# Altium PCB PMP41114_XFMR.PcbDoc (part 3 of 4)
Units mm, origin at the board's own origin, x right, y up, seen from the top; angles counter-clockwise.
Board outline 70 x 173.04 mm, 10 copper layers (Top Layer, Layer 2, Layer 3, Layer 4, Layer 5, Layer 6, Layer 7, Layer 8, Layer 9, Bottom Layer 1), stack 2.98 mm thick; 147 components, 149 nets, 547 pads, 972 vias.
Unrouted connection lines stored in the file: 2.
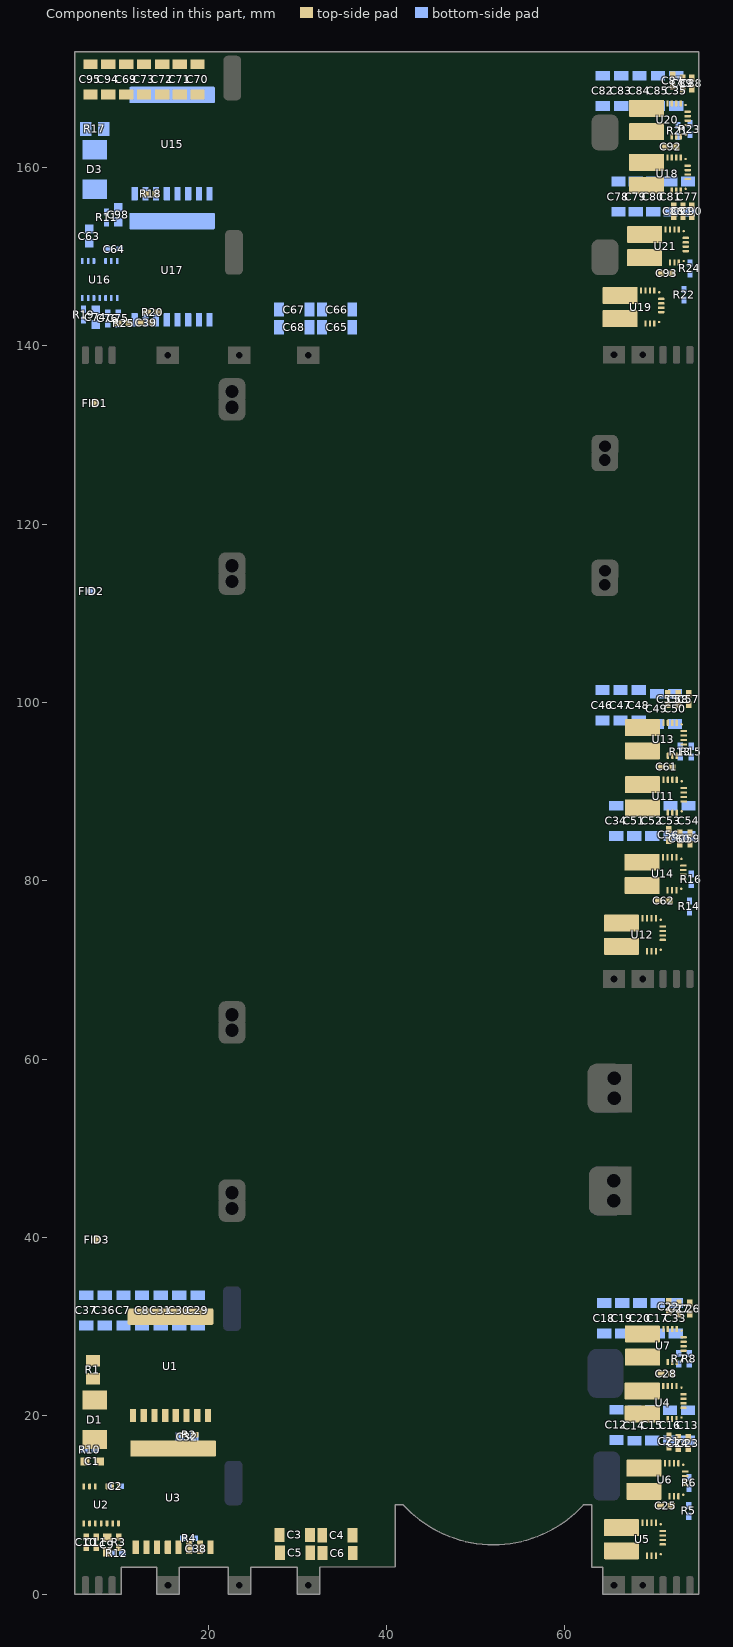
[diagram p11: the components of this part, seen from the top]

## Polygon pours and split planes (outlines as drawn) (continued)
Pri-Middle_2 on Layer 3 "LAYER_3_PRI-MIDDLE_2_P393" (solid, remove dead copper, pour order 393): 33.543,7.627 33.956,7.214 33.956,3.473 31.984,1.5 29.993,1.5 29.993,7.094 30.526,7.627
no net on Layer 5 "LAYER_5_NONET_P415" (solid, remove dead copper, pour order 415): 5.5,9.945 8.693,13.138 10.372,13.138 10.473,13.037 10.473,3.377 9.839,2.743 9.839,0.768 5.532,0.768 5.5,0.8
Pri-Mid1_2 on Layer 5 "LAYER_5_PRI-MID1_2_P625" (solid, remove dead copper, pour order 625): 18 vertices, not listed, extent 22.496,3.231 37.639,14.568
Pri-Mid1_5 on Layer 5 "LAYER_5_PRI-MID1_5_P622" (solid, remove dead copper, pour order 622): 28.819,141.744 26.926,141.744 26.926,147.57 37.473,147.57 37.473,146.475 37.473,141.522 34.617,141.522 34.617,145.888 34.12,146.385 29.713,146.385 29.107,145.78 29.107,142.032
Pri-SW_5 on Layer 5 "LAYER_5_PRI-SW_5_P468" (solid, remove dead copper, pour order 468): 49 vertices, not listed, extent 21.519,143.513 62.713,170.403
54Vout_5 on Layer 5 "LAYER_5_54VOUT_5_P589" (solid, remove dead copper, pour order 589): 63.146,172.5 63.146,157.183 64.767,157.183 64.767,154.137 63.146,154.137 63.146,141.018 64.25,141.018 64.25,138 75,138 75,172.5
54Vout_2 on Layer 5 "LAYER_5_54VOUT_2_P435" (solid, remove dead copper, pour order 435): 63.394,34.5 63.394,19.183 64.767,19.183 64.767,16.137 63.394,16.137 63.394,3.018 64.25,3.018 64.25,0 75,0 75,34.5
54Vout_4 on Layer 5 "LAYER_5_54VOUT_4_P568" (solid, remove dead copper, pour order 568): 63,103 63,89.592 65.232,89.592 65.232,80.979 63,78.747 63,71.018 64.25,71.018 64.25,68 75,68 75,103
Pri-Middle_5 on Layer 5 "LAYER_5_PRI-MIDDLE_5_P559" (solid, remove dead copper, pour order 559): 33.543,145.589 33.956,145.175 33.956,141.04 32.563,141.04 32.5,140.962 32.5,139.462 29.993,139.462 29.993,145.055 30.526,145.589
Pri-SW_2 on Layer 5 "LAYER_5_PRI-SW_2_P454" (solid, remove dead copper, pour order 454): 40 vertices, not listed, extent 36.298,37.799 64.006,64.687
B-_5 on Layer 5 "LAYER_5_B-_5_P534" (solid, remove dead copper, pour order 534): 4.985,141.046 5.001,147.544 5.437,147.544 8.397,150.504 20.543,150.504 20.543,141.742 19.807,141.006 16.771,141.006 16.771,138.962 14.155,138.962 14.155,141.046
B-_5 on Layer 5 "LAYER_5_B-_5_P519" (solid, remove dead copper, pour order 519): 5.498,172.468 21.325,172.468 21.325,170.307 5.498,170.307
B+_5 on Layer 5 "Layer 5-B+_5" (solid, remove dead copper, pour order 513): 5.5,151.038 21.238,151.038 21.238,140.962 22.243,140.962 22.243,139.303 24.784,139.303 24.784,140.962 26.28,140.962 26.28,151.862 20.899,155.75 20.899,169.482 5.5,169.482
Sec-SWB_4 on Layer 5 "LAYER_5_SEC-SWB_4_P497" (solid, remove dead copper, pour order 497): 34 vertices, not listed, extent 38.632,73.616 70.621,100.504
Pri-SW_5 on Layer 5 "LAYER_5_PRI-SW_5_P486" (solid, remove dead copper, pour order 486): 35 vertices, not listed, extent 37.639,107.799 63.766,134.687
B-_5 on Layer 5 "LAYER_5_B-_5_P480" (solid, remove dead copper, pour order 480): 14.226,139.303 14.226,140.757 14.431,140.962 16.766,140.962 16.766,139.303
Pri-SW_2 on Layer 5 "LAYER_5_PRI-SW_2_P457" (solid, remove dead copper, pour order 457): 5.514,28.855 21.197,28.855 21.197,19.697 16.802,15.302 5.498,15.302
B-_2 on Layer 5 "LAYER_5_B-_2_P456" (solid, remove dead copper, pour order 456): 5.531,34.439 21.097,34.439 21.097,33.254 5.531,33.254
Pri-SW_2 on Layer 5 "LAYER_5_PRI-SW_2_P452" (solid, remove dead copper, pour order 452): 40 vertices, not listed, extent 22.666,5.484 62.746,32.374
B+_5 on Layer 5 "LAYER_5_B+_5_P449" (solid, remove dead copper, pour order 449): 22.243,139.303 22.243,140.757 22.448,140.962 24.784,140.962 24.784,139.303
B+_2 on Layer 5 "LAYER_5_B+_2_P444" (solid, remove dead copper, pour order 444): 22.243,1.342 22.243,2.795 22.448,3 24.784,3 24.784,1.342
B-_2 on Layer 5 "LAYER_5_B-_2_P420" (solid, remove dead copper, pour order 420): 10.913,14.523 21.607,14.523 21.607,3.904 20.703,3 16.78,3 16.78,0 14.231,0 14.231,3.039 11.311,3.039 10.878,3.473
Pri-Middle_2 on Layer 5 "LAYER_5_PRI-MIDDLE_2_P395" (solid, remove dead copper, pour order 395): 33.543,7.627 33.956,7.214 33.956,3.473 31.984,1.5 29.993,1.5 29.993,7.094 30.526,7.627
12Vp_5 on Layer 8 "LAYER_8_12VP_5_P509" (solid, remove dead copper, pour order 509): 5,138.25 5,145.99 7.47,148.46 10.61,148.46 10.61,141.311 10.25,140.951 10.25,138.25
Pri-Mid1_2 on Layer 8 "LAYER_8_PRI-MID1_2_P628" (solid, remove dead copper, pour order 628): 28.985,3.454 27.118,3.454 27.118,9.203 37.639,9.203 37.639,8.185 37.639,3.231 34.783,3.231 34.783,7.598 34.286,8.095 29.878,8.095 29.273,7.489 29.273,3.742
B+_2 on Layer 8 "LAYER_8_B+_2_P423" (solid, remove dead copper, pour order 423): 5.563,14.288 20.751,14.288 21.336,13.703 21.336,3 22.243,3 22.243,1.492 26.4,1.492 26.4,31.588 5.563,31.588
Pri-Mid1_5 on Layer 8 "LAYER_8_PRI-MID1_5_P621" (solid, remove dead copper, pour order 621): 28.819,141.744 26.86,141.744 26.86,147.57 37.473,147.57 37.473,146.475 37.473,141.522 34.617,141.522 34.617,145.888 34.12,146.385 29.713,146.385 29.107,145.78 29.107,142.032
PGND_5 on Layer 8 "LAYER_8_PGND_5_P613" (solid, remove dead copper, pour order 613): 65.704,153.3 71,153.3 71,151.463 67.045,151.463 65.704,152.803
Pri-SW_2 on Layer 8 "LAYER_8_PRI-SW_2_P391" (solid, remove dead copper, pour order 391): 46 vertices, not listed, extent 22.666,37.531 64.006,64.488
54Vout_5 on Layer 8 "LAYER_8_54VOUT_5_P594" (solid, remove dead copper, pour order 594): 63,172.5 63,157.25 64.826,157.25 64.826,154.422 65.704,153.543 71.302,153.543 71.302,144.262 63,144.262 63,141.018 64.25,141.018 64.25,138 75,138 75,172.5
54Vout_4 on Layer 8 "LAYER_8_54VOUT_4_P593" (solid, remove dead copper, pour order 593): 63,102.5 63,87.183 64.767,87.183 64.767,84.137 63,84.137 63,71.018 64.25,71.018 64.25,68 75,68 75,102.5
Pri-Middle_5 on Layer 8 "LAYER_8_PRI-MIDDLE_5_P562" (solid, remove dead copper, pour order 562): 33.543,145.589 33.956,145.175 33.956,141.04 32.563,141.04 32.5,140.962 32.5,139.462 29.993,139.462 29.993,145.055 30.526,145.589
B-_5 on Layer 8 "LAYER_8_B-_5_P514" (solid, remove dead copper, pour order 514): 10.775,150.412 20.4,150.412 20.557,150.254 20.557,140.962 10.775,140.962
B+_5 on Layer 8 "Layer 8-B+_5" (solid, remove dead copper, pour order 512): 5.5,151.038 20.649,151.038 21.238,150.449 21.238,140.962 22.243,140.962 22.243,139.303 24.784,139.303 24.784,140.962 26.28,140.962 26.28,156.717 24.079,159.071 24.079,166.587 21.892,168.023 21.892,169.482 5.5,169.482
54Vout_2 on Layer 8 "LAYER_8_54VOUT_2_P502" (solid, remove dead copper, pour order 502): 63,34.5 63,19.183 64.767,19.183 64.767,16.137 63,16.137 63,3.018 64.25,3.018 64.25,0 75,0 75,34.5
B-_5 on Layer 8 "LAYER_8_B-_5_P501" (solid, remove dead copper, pour order 501): 5.498,172.468 21.719,172.468 21.719,170.307 5.498,170.307
B+_5 on Layer 8 "LAYER_8_B+_5_P500" (solid, remove dead copper, pour order 500): 5.479,169.47 19.486,169.47 19.75,169.206 19.75,167.796 19.264,167.309 5.479,167.309
Pri-SW_5 on Layer 8 "LAYER_8_PRI-SW_5_P472" (solid, remove dead copper, pour order 472): 44 vertices, not listed, extent 22.666,107.493 63.785,134.449
Sec-SWB_4 on Layer 8 "LAYER_8_SEC-SWB_4_P496" (solid, remove dead copper, pour order 496): 43 vertices, not listed, extent 38.632,73.539 71.046,100.428
B-_5 on Layer 8 "LAYER_8_B-_5_P481" (solid, remove dead copper, pour order 481): 14.226,139.303 14.226,140.757 14.431,140.962 16.766,140.962 16.766,139.303
Sec-SWA_5 on Layer 8 "LAYER_8_SEC-SWA_5_P477" (solid, remove dead copper, pour order 477): 40 vertices, not listed, extent 38.66,143.521 71.051,170.41
B-_2 on Layer 8 "LAYER_8_B-_2_P464" (solid, remove dead copper, pour order 464): 5.498,34.439 19.486,34.439 19.75,34.174 19.75,32.764 19.264,32.278 5.498,32.278
B+_2 on Layer 8 "LAYER_8_B+_2_P463" (solid, remove dead copper, pour order 463): 5.479,31.441 19.486,31.441 19.75,31.176 19.75,29.766 19.264,29.28 5.479,29.28
Sec-SWA_2 on Layer 8 "LAYER_8_SEC-SWA_2_P384" (solid, remove dead copper, pour order 384): 43 vertices, not listed, extent 39.371,5.539 71.046,32.428
B+_2 on Layer 8 "LAYER_8_B+_2_P445" (solid, remove dead copper, pour order 445): 22.243,1.342 22.243,2.795 22.448,3 24.784,3 24.784,1.342
B-_2 on Layer 8 "LAYER_8_B-_2_P429" (solid, remove dead copper, pour order 429): 10.938,13.198 20.598,13.198 20.598,3.946 19.36,2.708 16.75,2.708 16.75,0.663 14.231,0.663 14.231,3 10.913,3
12Vp_2 on Layer 8 "LAYER_8_12VP_2_P418" (solid, remove dead copper, pour order 418): 5.5,9.945 8.693,13.138 10.372,13.138 10.473,13.037 10.473,3.377 9.839,2.743 9.839,0.768 5.532,0.768 5.5,0.8
Pri-Middle_2 on Layer 8 "LAYER_8_PRI-MIDDLE_2_P397" (solid, remove dead copper, pour order 397): 33.543,7.627 33.956,7.214 33.956,3.473 31.984,1.5 29.993,1.5 29.993,7.094 30.526,7.627
Sec-SWB_4 on Bottom Layer 1 "BOTTOM_LAYER_1_SEC-SWB_4_P567" (solid, remove dead copper, pour order 567): 70.718,80.507 67.022,80.507 66.715,80.814 66.715,83.256 66.639,83.332 64.423,83.332 62.789,81.699 62.789,74.632 63.232,74.19 70.176,74.19 70.718,74.731
54Vout_5 on Bottom Layer 1 "BOTTOM_LAYER_1_54VOUT_5_P556" (solid, remove dead copper, pour order 556): 63.625,143.991 68.731,143.991 68.731,142.482 66.876,140.627 66.868,138.117 64.25,138.117 64.25,140.881 63.625,140.881
54Vout_4 on Bottom Layer 1 "BOTTOM_LAYER_1_54VOUT_4_P555" (solid, remove dead copper, pour order 555): 63.625,73.711 70.16,73.711 70.16,73.589 66.875,70.304 66.868,68.117 64.25,68.117 64.25,70.881 63.625,70.881
PGND_4 on Bottom Layer 1 "BOTTOM_LAYER_1_PGND_4_P566" (solid, remove dead copper, pour order 566): 64.951,86.072 74.518,86.072 75.011,85.579 75.011,68.042 67.402,68.042 67.402,70.256 71.057,73.912 71.057,80.912 70.898,81.071 67.34,81.071 67.11,81.3 67.11,83.524 66.888,83.746 64.951,83.746
Pri-Middle_5 on Bottom Layer 1 "BOTTOM_LAYER_1_PRI-MIDDLE_5_P564" (solid, remove dead copper, pour order 564): 33.543,145.589 33.956,145.175 33.956,141.04 32.563,141.04 32.5,140.962 32.5,139.462 29.993,139.462 29.993,145.055 30.526,145.589
54Vout_5 on Bottom Layer 1 "BOTTOM_LAYER_1_54VOUT_5_P554" (solid, remove dead copper, pour order 554): 63.232,172.709 74.754,172.709 74.754,170.211 74.298,169.756 63.533,169.756 63.244,170.045
54Vout_4 on Bottom Layer 1 "BOTTOM_LAYER_1_54VOUT_4_P553" (solid, remove dead copper, pour order 553): 63.233,102.5 74.754,102.5 74.754,100.211 74.298,99.756 63.533,99.756 63.244,100.045
B-_5 on Bottom Layer 1 "BOTTOM_LAYER_1_B-_5_P531" (solid, remove dead copper, pour order 531): 4.98,141.039 4.996,147.538 6.167,147.538 8.392,149.763 8.392,151.273 20.538,151.273 20.538,141.735 19.802,141 16.766,141 16.766,138.955 14.15,138.955 14.15,141.039
PGND_5 on Bottom Layer 1 "BOTTOM_LAYER_1_PGND_5_P544" (solid, remove dead copper, pour order 544): 65.209,155.661 74.857,155.661 74.857,151.425 63.437,151.425 63.437,152.011 65.209,153.525
Sec-SWA_5 on Bottom Layer 1 "BOTTOM_LAYER_1_SEC-SWA_5_P475" (solid, remove dead copper, pour order 475): 36 vertices, not listed, extent 40.77,143.519 71.407,170.408
54Vout_5 on Bottom Layer 1 "BOTTOM_LAYER_1_54VOUT_5_P541" (solid, remove dead copper, pour order 541): 65.175,156.835 74.674,156.835 74.674,158.466 74.167,158.973 66.015,158.973 65.175,158.133
PGND_5 on Bottom Layer 1 "BOTTOM_LAYER_1_PGND_5_P539" (solid, remove dead copper, pour order 539): 63.168,165.54 75.018,165.54 75.018,168.163 63.168,168.163
Sec-SWA_5 on Bottom Layer 1 "BOTTOM_LAYER_1_SEC-SWA_5_P543" (solid, remove dead copper, pour order 543): 72.681,150.913 72.681,145.889 71.212,144.419 63.437,144.419 63.437,150.913
B+_5 on Bottom Layer 1 "BOTTOM_LAYER_1_B+_5_P511" (solid, remove dead copper, pour order 511): 5.481,169.45 20.813,169.45 20.813,167.29 5.481,167.29
B-_5 on Bottom Layer 1 "BOTTOM_LAYER_1_B-_5_P510" (solid, remove dead copper, pour order 510): 5.498,172.468 20.83,172.468 20.83,170.307 5.498,170.307
PGND_4 on Bottom Layer 1 "BOTTOM_LAYER_1_PGND_4_P494" (solid, remove dead copper, pour order 494): 63.234,98.53 74.623,98.53 74.623,96.284 74.44,96.101 63.391,96.101 63.244,96.249
54Vout_4 on Bottom Layer 1 "BOTTOM_LAYER_1_54VOUT_4_P493" (solid, remove dead copper, pour order 493): 65.003,89.252 74.498,89.252 74.691,89.059 74.691,87 65.003,87
Sec-SWB_4 on Bottom Layer 1 "BOTTOM_LAYER_1_SEC-SWB_4_P492" (solid, remove dead copper, pour order 492): 35 vertices, not listed, extent 40.128,73.519 71.723,100.408
B-_5 on Bottom Layer 1 "BOTTOM_LAYER_1_B-_5_P478" (solid, remove dead copper, pour order 478): 14.226,139.303 14.226,140.757 14.614,141.145 16.583,141.145 16.766,140.962 16.766,139.303
Pri-SW_5 on Bottom Layer 1 "BOTTOM_LAYER_1_PRI-SW_5_P460" (solid, remove dead copper, pour order 460): 10.377,152.73 21.719,152.73 23.676,154.687 23.676,164.049 23.22,164.505 10.377,164.505
Sec-SWA_2 on Bottom Layer 1 "BOTTOM_LAYER_1_SEC-SWA_2_P383" (solid, remove dead copper, pour order 383): 36 vertices, not listed, extent 40.128,5.519 70.719,32.408
B+_5 on Bottom Layer 1 "BOTTOM_LAYER_1_B+_5_P447" (solid, remove dead copper, pour order 447): 22.243,139.303 22.243,140.757 22.631,141.145 24.6,141.145 24.784,140.962 24.784,139.303
PGND_2 on Bottom Layer 1 "BOTTOM_LAYER_1_PGND_2_P438" (solid, remove dead copper, pour order 438): 63.233,30.704 73.53,30.704 73.53,28.974 72.516,27.96 63.533,27.96 63.244,28.249
54Vout_2 on Bottom Layer 1 "BOTTOM_LAYER_1_54VOUT_2_P437" (solid, remove dead copper, pour order 437): 63.233,34.5 74.754,34.5 74.754,32.211 74.298,31.756 63.533,31.756 63.244,32.045
54Vout_2 on Bottom Layer 1 "BOTTOM_LAYER_1_54VOUT_2_P432" (solid, remove dead copper, pour order 432): 63.625,5.872 71.365,5.872 71.365,5.281 70.57,4.539 70.57,3.743 68.154,3.743 66.868,2.457 66.868,0.135 64.25,0.135 64.25,2.899 63.625,2.899
Pri-Mid1_2 on Bottom Layer 1 "BOTTOM_LAYER_1_PRI-MID1_2_P408" (solid, remove dead copper, pour order 408): 21.821,8.378 22.243,7.955 23.571,7.955 23.851,8.235 23.851,14.54 23.48,14.911 22.414,14.911 21.821,14.317
Pri-Middle_2 on Bottom Layer 1 "BOTTOM_LAYER_1_PRI-MIDDLE_2_P405" (solid, remove dead copper, pour order 405): 30.837,7.42 33.31,7.42 33.368,7.363 33.368,3.773 32.294,2.7 32.294,1 29.993,1 29.993,2.931 30.26,3.198 30.26,6.843
B-_2 on Bottom Layer 1 "BOTTOM_LAYER_1_B-_2_P404" (solid, remove dead copper, pour order 404): 5.498,34.439 19.486,34.439 19.75,34.174 19.75,32.764 19.264,32.278 5.498,32.278
B+_2 on Bottom Layer 1 "BOTTOM_LAYER_1_B+_2_P403" (solid, remove dead copper, pour order 403): 5.479,31.441 19.486,31.441 19.75,31.176 19.75,29.766 19.264,29.28 5.479,29.28
Pri-SW_2 on Bottom Layer 1 "BOTTOM_LAYER_1_PRI-SW_2_P402" (solid, remove dead copper, pour order 402): 5.573,27.595 23.41,27.595 23.41,17.491 22.797,16.878 5.548,16.878
B-_2 on Bottom Layer 1 "BOTTOM_LAYER_1_B-_2_P401" (solid, remove dead copper, pour order 401): 5.007,3.039 5.027,11.17 9.309,11.17 9.879,11.74 9.879,14.686 20.565,14.686 20.565,3.735 16.75,3.735 16.75,0.955 14.231,0.955 14.231,3.039
PGND_2 on Bottom Layer 1 "BOTTOM_LAYER_1_PGND_2_P386" (solid, remove dead copper, pour order 386): 65.003,17.86 74.677,17.86 75,17.537 75,13.087 72.16,13.087 67.27,13.087 67.099,13.258 67.099,15.935 66.468,16.566 65.003,16.566
Sec-SWA_2 on Bottom Layer 1 "BOTTOM_LAYER_1_SEC-SWA_2_P385" (solid, remove dead copper, pour order 385): 72.87,12.557 67.023,12.557 66.716,12.863 66.716,15.306 66.096,15.926 63.296,15.926 62.791,15.421 62.791,6.682 63.121,6.351 72.519,6.351 72.87,6.702
Sec-SWA_2 on Bottom Layer 1 "BOTTOM_LAYER_1_SEC-SWA_2_P380" (solid, remove dead copper, pour order 380): 62.491,27.614 71.938,27.614 71.938,21.799 63.098,21.799 62.491,22.406
54Vout_2 on Bottom Layer 1 "BOTTOM_LAYER_1_54VOUT_2_P379" (solid, remove dead copper, pour order 379): 65.003,21.252 74.498,21.252 74.75,21 74.75,19.598 74.5,19.348 65.003,19.348
no net on Layer 2 "LAYER_2_NONET_P413" (solid, remove dead copper, pour order 413): 5.5,9.945 8.832,13.277 10.233,13.277 10.473,13.037 10.473,3.377 9.839,2.743 9.839,0.768 5.532,0.768 5.5,0.8
Pri-Mid1_2 on Layer 2 "LAYER_2_PRI-MID1_2_P631" (solid, remove dead copper, pour order 631): 18 vertices, not listed, extent 22.753,3.231 37.639,14.568
Pri-Middle_5 on Layer 2 "LAYER_2_PRI-MIDDLE_5_P620" (solid, remove dead copper, pour order 620): 33.543,145.589 33.956,145.175 33.956,141.04 32.563,141.04 32.5,140.962 32.5,139.462 29.993,139.462 29.993,145.055 30.526,145.589
Pri-Mid1_5 on Layer 2 "LAYER_2_PRI-MID1_5_P618" (solid, remove dead copper, pour order 618): 18 vertices, not listed, extent 22.33,141.522 37.473,152.859
Pri-SW_5 on Layer 2 "LAYER_2_PRI-SW_5_P610" (solid, remove dead copper, pour order 610): 22.5,120.5 45.032,120.5 46.825,117.549 46.825,115.966 42.882,115.966 40.128,116.107 37.826,116.372 34.277,115.263 30.142,115.087 26.646,116.107 26.646,111.972 26.581,111.907 22.5,111.907
Pri-SW_5 on Layer 2 "LAYER_2_PRI-SW_5_P483" (solid, remove dead copper, pour order 483): 27.39,157.328 22.317,157.328 22.317,172.5 25.989,172.5 26.425,172.064 26.425,166.233 27.389,165.27 27.431,162.115 24.983,162.085 24.632,161.734 24.632,160.446 24.991,160.087 27.459,160.091 27.459,157.602
Pri-SW_5 on Layer 2 "LAYER_2_PRI-SW_5_P527" (solid, remove dead copper, pour order 527): 5.379,165.772 21.519,165.772 21.519,154.774 19.687,152.942 5.348,152.942
54Vout_4 on Layer 2 "LAYER_2_54VOUT_4_P577" (solid, remove dead copper, pour order 577): 63.233,99.57 74.754,99.57 74.754,102.647 63.233,102.647
54Vout_5 on Layer 2 "Layer 2-54Vout_5" (solid, remove dead copper, pour order 595): 63.481,141.301 64.25,141.301 64.25,138 66.987,138 66.987,141.301 70.815,141.301 70.883,169.313 63.233,169.313 63.233,159.132 65.112,157.254 65.112,153.279 63.481,153.279
54Vout_5 on Layer 2 "LAYER_2_54VOUT_5_P580" (solid, remove dead copper, pour order 580): 63.233,169.57 74.754,169.57 74.754,172.5 63.233,172.5
AGND_5 on Layer 2 "LAYER_2_AGND_5_P579" (solid, remove dead copper, pour order 579): 75,169.343 75,138 70.9,138 70.9,169.343
54Vout_4 on Layer 2 "Layer 2-54Vout_4" (solid, remove dead copper, pour order 578): 63.224,71.301 64.25,71.301 64.25,68 66.987,68 66.987,71.301 70.566,71.301 70.634,99.313 64.66,99.313 64.66,87.705 65.112,87.254 65.112,83.279 63.224,83.279
AGND_4 on Layer 2 "LAYER_2_AGND_4_P576" (solid, remove dead copper, pour order 576): 75,99.343 75,68 70.547,68 70.547,99.343
PGND_2 on Layer 2 "Layer 2-PGND_2" (solid, remove dead copper, pour order 575): 63,3.301 67.103,3.301 67.103,0 70.483,0 70.483,31.313 63.233,31.313 63.233,21.132 65.112,19.254 65.112,15.279 63,15.279
AGND_2 on Layer 2 "LAYER_2_AGND_2_P382" (solid, remove dead copper, pour order 382): 75,31.343 75,0 70.214,0 70.214,4.13 70.774,4.69 70.774,31.343
Pri-SW_2 on Layer 2 "LAYER_2_PRI-SW_2_P369" (solid, pour order 369): 41 vertices, not listed, extent 22.5,37.43 64.006,66.5
B-_5 on Layer 2 "LAYER_2_B-_5_P526" (solid, remove dead copper, pour order 526): 4.98,141.039 4.996,147.538 6.167,147.538 8.392,149.763 8.392,151.273 20.538,151.273 20.538,141.735 19.802,141 16.766,141 16.766,138.955 14.15,138.955 14.15,141.039
B-_5 on Layer 2 "LAYER_2_B-_5_P525" (solid, remove dead copper, pour order 525): 5.504,172.439 20.641,172.439 20.839,172.241 20.839,170.9 5.504,170.9
B+_5 on Layer 2 "LAYER_2_B+_5_P524" (solid, remove dead copper, pour order 524): 5.478,169.47 20.49,169.47 20.83,169.13 20.83,167.309 5.478,167.309
Sec-SWB_4 on Layer 2 "LAYER_2_SEC-SWB_4_P491" (solid, remove dead copper, pour order 491): 39 vertices, not listed, extent 38.688,73.519 64.66,100.408
B-_5 on Layer 2 "LAYER_2_B-_5_P479" (solid, remove dead copper, pour order 479): 14.226,139.303 14.226,140.757 14.614,141.145 16.583,141.145 16.766,140.962 16.766,139.303
Sec-SWA_5 on Layer 2 "LAYER_2_SEC-SWA_5_P474" (solid, remove dead copper, pour order 474): 39 vertices, not listed, extent 39.371,143.519 64.66,170.408
Sec-SWA_2 on Layer 2 "LAYER_2_SEC-SWA_2_P373" (solid, remove dead copper, pour order 373): 39 vertices, not listed, extent 39.371,5.519 64.66,32.408
B+_5 on Layer 2 "LAYER_2_B+_5_P448" (solid, remove dead copper, pour order 448): 22.243,139.303 22.243,140.757 22.631,141.145 24.6,141.145 24.784,140.962 24.784,139.303
B+_2 on Layer 2 "LAYER_2_B+_2_P443" (solid, remove dead copper, pour order 443): 22.243,1.342 22.243,2.795 22.631,3.183 24.6,3.183 24.784,3 24.784,1.342
Pri-Middle_2 on Layer 2 "LAYER_2_PRI-MIDDLE_2_P392" (solid, remove dead copper, pour order 392): 33.543,7.627 33.956,7.214 33.956,3.473 31.984,1.5 29.993,1.5 29.993,7.094 30.526,7.627
54Vout_2 on Layer 2 "LAYER_2_54VOUT_2_P387" (solid, remove dead copper, pour order 387): 63.233,31.57 74.754,31.57 74.754,34.5 63.233,34.5
B-_2 on Layer 2 "LAYER_2_B-_2_P367" (solid, remove dead copper, pour order 367): 10.678,13.081 5.515,18.244 5.593,34.409 21.998,34.409 21.998,3.869 19.629,1.5 12.113,1.5 10.678,2.935
Pri-Mid1_5 on Layer 4 "LAYER_4_PRI-MID1_5_P623" (solid, remove dead copper, pour order 623): 28.819,141.744 26.926,141.744 26.926,147.57 37.473,147.57 37.473,146.475 37.473,141.522 34.617,141.522 34.617,145.888 34.12,146.385 29.713,146.385 29.107,145.78 29.107,142.032
B+_5 on Layer 4 "Layer 3-B+_5" (solid, remove dead copper, pour order 616): 5.5,151.038 21.238,151.038 21.238,140.962 22.243,140.962 22.243,139.303 24.784,139.303 24.784,140.962 26.28,140.962 26.28,152.031 20.899,155.534 20.899,169.482 5.5,169.482
Pri-SW_2 on Layer 4 "LAYER_4_PRI-SW_2_P389" (solid, remove dead copper, pour order 389): 45 vertices, not listed, extent 37.67,37.431 64.006,64.624
Pri-SW_5 on Layer 4 "LAYER_4_PRI-SW_5_P614" (solid, remove dead copper, pour order 614): 33 vertices, not listed, extent 41,107.799 63.766,134.687
54Vout_4 on Layer 4 "LAYER_4_54VOUT_4_P588" (solid, remove dead copper, pour order 588): 65.285,89.4 70.5,89.4 70.647,89.252 70.647,87.673 70.367,87.392 65.376,87.392 65.051,87.717 65.051,89.16 65.286,89.394
PGND_5 on Layer 4 "LAYER_4_PGND_5_P587" (solid, remove dead copper, pour order 587): 74.883,172.71 74.883,138.21 67.153,138.21 67.153,141.511 63.164,141.511 63.164,152.684 63.164,159.199 63.164,172.71
PGND_4 on Layer 4 "LAYER_4_PGND_4_P586" (solid, remove dead copper, pour order 586): 75,102.5 75,68 67.27,68 67.27,71.301 63.282,71.301 63.282,79.037 65.151,80.906 65.151,86.999 70.395,86.999 71.046,87.65 71.046,96.123 63.282,96.123 63.282,102.5
B-_5 on Layer 4 "LAYER_4_B-_5_P535" (solid, remove dead copper, pour order 535): 4.985,141.046 5.001,147.544 6.172,147.544 8.397,149.769 8.397,151.279 20.543,151.279 20.543,141.742 19.807,141.006 16.771,141.006 16.771,138.962 14.155,138.962 14.155,141.046
B+_5 on Layer 4 "LAYER_4_B+_5_P530" (solid, remove dead copper, pour order 530): 5.498,169.581 20.538,169.581 20.538,167.42 5.498,167.42
B-_5 on Layer 4 "LAYER_4_B-_5_P529" (solid, remove dead copper, pour order 529): 5.498,172.468 21.325,172.468 21.325,170.307 5.498,170.307
Sec-SWB_4 on Layer 4 "LAYER_4_SEC-SWB_4_P503" (solid, remove dead copper, pour order 503): 35 vertices, not listed, extent 38.632,73.616 70.621,100.504
Pri-Middle_5 on Layer 4 "LAYER_4_PRI-MIDDLE_5_P489" (solid, remove dead copper, pour order 489): 33.543,145.589 33.956,145.175 33.956,141.04 32.563,141.04 32.5,140.962 32.5,139.462 29.993,139.462 29.993,145.055 30.526,145.589
Pri-SW_5 on Layer 4 "LAYER_4_PRI-SW_5_P469" (solid, remove dead copper, pour order 469): 52 vertices, not listed, extent 21.519,143.513 62.597,170.403
Pri-SW_2 on Layer 4 "LAYER_4_PRI-SW_2_P459" (solid, remove dead copper, pour order 459): 22.666,29.431 22.666,34.224 22.851,34.409 24.619,34.409 24.784,34.244 24.784,30.201
Pri-Mid1_2 on Layer 4 "LAYER_4_PRI-MID1_2_P458" (solid, remove dead copper, pour order 458): 18 vertices, not listed, extent 22.496,3.231 37.639,14.568
Pri-SW_2 on Layer 4 "LAYER_4_PRI-SW_2_P364" (solid, remove dead copper, pour order 364): 48 vertices, not listed, extent 5.506,5.484 62.622,32.374
PGND_2 on Layer 4 "LAYER_4_PGND_2_P381" (solid, remove dead copper, pour order 381): 75,34.5 75,0 67.27,0 67.27,3.301 63.282,3.301 63.282,14.474 63.282,20.989 63.282,34.5
B-_2 on Layer 4 "LAYER_4_B-_2_P422" (solid, remove dead copper, pour order 422): 10.908,14.601 21.601,14.601 21.601,4.546 16.78,4.546 16.78,0.955 14.231,0.955 14.231,3.039 10.88,3.039
12Vp_2 on Layer 4 "LAYER_4_12VP_2_P414" (solid, remove dead copper, pour order 414): 8.493,13.286 10.888,13.286 10.843,4.898 10.843,3.099 10.156,3.06 10.156,1.012 9.944,0.8 5.5,0.8 5.5,9.874 8.493,12.867
B-_2 on Layer 4 "LAYER_4_B-_2_P412" (solid, remove dead copper, pour order 412): 5.531,34.439 21.945,34.439 21.945,33.254 5.531,33.254
Pri-Middle_2 on Layer 4 "LAYER_4_PRI-MIDDLE_2_P394" (solid, remove dead copper, pour order 394): 33.543,7.627 33.956,7.214 33.956,3.473 31.984,1.5 29.993,1.5 29.993,7.094 30.526,7.627
Sec-SWA_2 on Layer 4 "LAYER_4_SEC-SWA_2_P388" (solid, remove dead copper, pour order 388): 70.529,27.614 70.774,27.369 70.774,22.127 70.446,21.799 67.233,21.799 66.973,22.058 66.973,27.316 67.271,27.614
no net on Layer 7 "LAYER_7_NONET_P416" (solid, remove dead copper, pour order 416): 5.5,9.945 8.693,13.138 10.372,13.138 10.473,13.037 10.473,3.377 9.839,2.743 9.839,0.768 5.532,0.768 5.5,0.8
Pri-Mid1_2 on Layer 7 "LAYER_7_PRI-MID1_2_P629" (solid, remove dead copper, pour order 629): 28.985,3.454 27.118,3.454 27.118,9.203 37.639,9.203 37.639,8.185 37.639,3.231 34.783,3.231 34.783,7.598 34.286,8.095 29.878,8.095 29.273,7.489 29.273,3.742
Pri-SW_2 on Layer 7 "LAYER_7_PRI-SW_2_P609" (solid, remove dead copper, pour order 609): 34 vertices, not listed, extent 37.503,37.531 64.006,64.488
54Vout_5 on Layer 7 "LAYER_7_54VOUT_5_P606" (solid, remove dead copper, pour order 606): 63.233,169.57 74.754,169.57 74.754,172.5 63.233,172.5
PGND_5 on Layer 7 "LAYER_7_PGND_5_P605" (solid, remove dead copper, pour order 605): 68.991,169.172 63,169.172 63,156.999 64.821,156.999 64.821,154.19 64.39,153.76 63.481,153.76 63.481,141.018 64.25,141.018 64.25,138 75,138 75,169.172
54Vout_4 on Layer 7 "LAYER_7_54VOUT_4_P604" (solid, remove dead copper, pour order 604): 63.233,99.57 74.754,99.57 74.754,102.5 63.233,102.5
PGND_4 on Layer 7 "LAYER_7_PGND_4_P603" (solid, remove dead copper, pour order 603): 68.991,99.172 63,99.172 63,87.312 64.821,87.312 64.821,84.19 64.39,83.76 63.481,83.76 63.481,71.018 64.25,71.018 64.25,68 75,68 75,99.172
54Vout_2 on Layer 7 "LAYER_7_54VOUT_2_P574" (solid, remove dead copper, pour order 574): 63.233,31.57 74.754,31.57 74.754,34.5 63.233,34.5
PGND_2 on Layer 7 "LAYER_7_PGND_2_P573" (solid, remove dead copper, pour order 573): 68.991,31.172 63,31.172 63,18.999 64.821,18.999 64.821,16.19 64.39,15.76 63.481,15.76 63.481,3.018 64.25,3.018 64.25,0 75,0 75,31.172
Pri-Middle_5 on Layer 7 "LAYER_7_PRI-MIDDLE_5_P561" (solid, remove dead copper, pour order 561): 33.543,145.589 33.956,145.175 33.956,141.04 32.563,141.04 32.5,140.962 32.5,139.462 29.993,139.462 29.993,145.055 30.526,145.589
B-_5 on Layer 7 "LAYER_7_B-_5_P532" (solid, remove dead copper, pour order 532): 4.98,141.039 4.996,147.538 6.167,147.538 8.392,149.763 8.392,151.273 20.538,151.273 20.538,141.735 19.802,141 16.766,141 16.766,138.955 14.15,138.955 14.15,141.039
Pri-Mid1_5 on Layer 7 "LAYER_7_PRI-MID1_5_P521" (solid, remove dead copper, pour order 521): 18 vertices, not listed, extent 22.33,141.522 37.473,152.859
B+_5 on Layer 7 "LAYER_7_B+_5_P516" (solid, remove dead copper, pour order 516): 5.498,169.581 21.719,169.581 21.719,167.42 5.498,167.42
B-_5 on Layer 7 "LAYER_7_B-_5_P515" (solid, remove dead copper, pour order 515): 5.498,172.468 21.719,172.468 21.719,170.307 5.498,170.307
Pri-SW_5 on Layer 7 "LAYER_7_PRI-SW_5_P466" (solid, remove dead copper, pour order 466): 54 vertices, not listed, extent 5.414,143.513 62.693,170.403
Sec-SWB_4 on Layer 7 "LAYER_7_SEC-SWB_4_P499" (solid, remove dead copper, pour order 499): 43 vertices, not listed, extent 38.632,73.539 71.046,100.428
Pri-SW_5 on Layer 7 "LAYER_7_PRI-SW_5_P484" (solid, remove dead copper, pour order 484): 34 vertices, not listed, extent 38,107.539 63.766,134.428
Pri-SW_2 on Layer 7 "LAYER_7_PRI-SW_2_P366" (solid, remove dead copper, pour order 366): 46 vertices, not listed, extent 22.851,5.484 63,34.409
B-_2 on Layer 7 "LAYER_7_B-_2_P431" (solid, remove dead copper, pour order 431): 5.515,34.219 5.735,34.439 22.243,34.439 22.243,33.254 5.515,33.254
B+_2 on Layer 7 "LAYER_7_B+_2_P425" (solid, remove dead copper, pour order 425): 5.5,13.715 20.8,13.715 21.238,13.277 21.238,3 22.243,3 22.243,1.492 26.28,1.492 26.28,14.549 22.373,18.727 22.373,32.579 5.5,32.579
B-_2 on Layer 7 "LAYER_7_B-_2_P424" (solid, remove dead copper, pour order 424): 10.904,12.861 20.565,12.861 20.565,4.238 19.327,3 16.75,3 16.75,0.955 14.231,0.955 14.231,3.039 10.88,3.039
Pri-Middle_2 on Layer 7 "LAYER_7_PRI-MIDDLE_2_P396" (solid, remove dead copper, pour order 396): 33.543,7.627 33.956,7.214 33.956,3.473 31.984,1.5 29.993,1.5 29.993,7.094 30.526,7.627
B-_5 on Layer 9 "LAYER_9_B-_5_P508" (solid, remove dead copper, pour order 508): 5,138 5,146.37 8.461,149.831 10.25,149.831 10.25,138
no net on Layer 9 "LAYER_9_NONET_P417" (solid, remove dead copper, pour order 417): 5.5,9.945 8.693,13.138 10.372,13.138 10.473,13.037 10.473,3.377 9.839,2.743 9.839,0.768 5.532,0.768 5.5,0.8
Pri-Mid1_2 on Layer 9 "LAYER_9_PRI-MID1_2_P627" (solid, remove dead copper, pour order 627): 18 vertices, not listed, extent 22.496,3.231 37.639,14.568
Sec-SWA_2 on Layer 9 "LAYER_9_SEC-SWA_2_P451" (solid, remove dead copper, pour order 451): 40 vertices, not listed, extent 39.371,5.519 64.701,32.408
54Vout_5 on Layer 9 "LAYER_9_54VOUT_5_P608" (solid, remove dead copper, pour order 608): 63.233,169.57 74.754,169.57 74.754,172.5 63.233,172.5
PGND_5 on Layer 9 "LAYER_9_PGND_5_P607" (solid, remove dead copper, pour order 607): 68.991,169.172 63.556,169.172 63.556,159.224 65.151,157.629 65.151,154.091 64.339,153.279 63,153.279 63,141.018 64.25,141.018 64.25,138 75,138 75,169.172
Sec-SWB_4 on Layer 9 "LAYER_9_SEC-SWB_4_P495" (solid, remove dead copper, pour order 495): 40 vertices, not listed, extent 38.632,73.519 64.697,100.408
54Vout_4 on Layer 9 "LAYER_9_54VOUT_4_P570" (solid, remove dead copper, pour order 570): 63.233,99.717 74.754,99.717 74.754,102.647 63.233,102.647
PGND_4 on Layer 9 "LAYER_9_PGND_4_P569" (solid, remove dead copper, pour order 569): 68.991,99.172 63,99.172 63,97.563 64.624,87.862 65.151,87.336 65.151,84.091 64.339,83.279 63,83.279 63,71.018 64.25,71.018 64.25,68 75,68 75,99.172
54Vout_2 on Layer 9 "LAYER_9_54VOUT_2_P436" (solid, remove dead copper, pour order 436): 63.233,31.57 74.754,31.57 74.754,34.5 63.233,34.5
Pri-Middle_5 on Layer 9 "LAYER_9_PRI-MIDDLE_5_P563" (solid, remove dead copper, pour order 563): 33.543,145.589 33.956,145.175 33.956,141.04 32.563,141.04 32.5,140.962 32.5,139.462 29.993,139.462 29.993,145.055 30.526,145.589
B-_5 on Layer 9 "Layer 9-B-_5" (solid, remove dead copper, pour order 538): 21.971,153.292 23.791,155.112 23.791,165.196 21.971,167.016 21.971,172.76 5.32,172.76 5.243,156.595 8.513,153.325 8.513,142.576 10.127,140.962 20.466,140.962 21.971,142.466
Pri-Mid1_5 on Layer 9 "LAYER_9_PRI-MID1_5_P520" (solid, remove dead copper, pour order 520): 18 vertices, not listed, extent 22.776,141.522 37.473,152.859
B-_5 on Layer 9 "LAYER_9_B-_5_P482" (solid, remove dead copper, pour order 482): 14.226,139.303 14.226,141.068 16.705,141.068 16.705,139.303
Sec-SWA_5 on Layer 9 "LAYER_9_SEC-SWA_5_P476" (solid, remove dead copper, pour order 476): 39 vertices, not listed, extent 39.371,143.519 64.66,170.408
Pri-SW_5 on Layer 9 "LAYER_9_PRI-SW_5_P471" (solid, remove dead copper, pour order 471): 46 vertices, not listed, extent 22.666,107.474 63.741,136.444
B-_2 on Layer 9 "LAYER_9_B-_2_P462" (solid, remove dead copper, pour order 462): 5.498,34.439 19.486,34.439 19.75,34.174 19.75,32.764 19.264,32.278 5.498,32.278
B+_2 on Layer 9 "LAYER_9_B+_2_P461" (solid, remove dead copper, pour order 461): 5.479,31.441 19.486,31.441 19.75,31.176 19.75,29.766 19.264,29.28 5.479,29.28
B+_5 on Layer 9 "LAYER_9_B+_5_P450" (solid, remove dead copper, pour order 450): 22.243,139.303 22.243,140.757 22.448,140.962 24.784,140.962 24.784,139.303
B+_2 on Layer 9 "LAYER_9_B+_2_P446" (solid, remove dead copper, pour order 446): 22.243,1.342 22.243,2.795 22.448,3 24.784,3 24.784,1.342
PGND_2 on Layer 9 "LAYER_9_PGND_2_P433" (solid, remove dead copper, pour order 433): 68.991,31.172 63.556,31.172 63.556,21.224 65.151,19.629 65.151,16.091 64.339,15.279 63.269,15.279 63.269,3.018 64.25,3.018 64.25,0 75,0 75,31.172
B-_2 on Layer 9 "LAYER_9_B-_2_P427" (solid, remove dead copper, pour order 427): 10.907,14.337 21.581,14.337 21.581,5.255 19.327,3 16.75,3 16.75,0.955 14.231,0.955 14.231,3.039 10.88,3.039
Pri-SW_2 on Layer 9 "LAYER_9_PRI-SW_2_P426" (solid, remove dead copper, pour order 426): 5.53,28.415 22.949,28.415 22.949,17.187 21.064,15.302 5.498,15.302
Pri-Middle_2 on Layer 9 "LAYER_9_PRI-MIDDLE_2_P398" (solid, remove dead copper, pour order 398): 33.543,7.627 33.956,7.214 33.956,3.473 31.984,1.5 29.993,1.5 29.993,7.094 30.526,7.627
B+_5 on Multi-Layer "TOP_LAYER_B+_P146" (solid, remove dead copper, pour order 146): 22.243,139.303 22.243,140.757 24.727,140.757 24.727,139.303
B-_5 on Multi-Layer "TOP_LAYER_B+_P146" (solid, remove dead copper): 14.226,139.303 14.226,140.928 14.443,141.145 16.583,141.145 16.78,140.948 16.78,139.303
Pri-Middle_5 on Multi-Layer "TOP_LAYER_PRI-MIDDLE_P191" (solid, remove dead copper, pour order 191): 29.973,139.303 29.973,140.757 30.361,141.145 32.33,141.145 32.513,140.962 32.513,139.303
PGND_5 on Multi-Layer "NONET_L-01_P-001" (solid, remove dead copper): 67.489,138.38 67.489,140.237 68.148,140.896 69.36,140.896 70,140.256 70,138.321 67.548,138.321
PGND_4 on Multi-Layer "NONET_L-01_P-001" (solid, remove dead copper): 67.489,68.38 67.489,70.273 68.113,70.896 69.311,70.896 70,70.207 70,68.321 67.548,68.321
PGND_2 on Multi-Layer "NONET_L-01_P-001" (solid, remove dead copper): 67.489,0.38 67.489,2.285 68.101,2.896 69.749,2.896 70,2.645 70,0.321 67.548,0.321

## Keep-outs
Keep-Out Layer:
  text ".Layer_Name" at 14.656,-21.806 h1.52

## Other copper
Top Layer:
  rectangle net Pri-Mid1_5: 35.367,141.888 37.268,145.456
  rectangle net Pri-Mid1_5: 26.765,141.714 28.534,145.608
  rectangle net 54Vout_5: 64.25,138.321 66.756,140.899
  rectangle net 54Vout_4: 64.25,68.321 66.756,70.899
  rectangle net 54Vout_2: 64.25,0.321 66.756,2.899
  rectangle net Pri-SW_2: 22.851,29.545 23.588,34.409
  rectangle net Pri-Mid1_2: 35.515,3.537 37.264,7.513
  rectangle net Pri-Mid1_2: 27.053,3.657 28.725,7.513
  text ".Layer_Name" at 14.656,-21.806 h1.52
Layer 3:
  rectangle net Pri-SW_5: 11.192,153.384 20.279,154.755
  rectangle net Pri-SW_2: 22.851,29.869 23.588,34.409
  rectangle net Pri-Mid1_2: 27.053,3.657 28.725,7.513
  rectangle net Pri-Mid1_2: 35.515,3.537 37.264,7.513
  rectangle net Pri-SW_2: 11.094,21.858 20.482,27.385
  pour cut-out: 19.486,17.926 cw(c19.486,18.646) 18.766,18.646 cw(c19.486,18.646) 19.486,19.366 cw(c19.486,18.646) 20.206,18.646 cw(c19.486,18.646)
  pour cut-out: 18.654,17.982 cw(c18.654,18.702) 17.934,18.702 cw(c18.654,18.702) 18.654,19.422 cw(c18.654,18.702) 19.374,18.702 cw(c18.654,18.702)
  pour cut-out: 17.865,18.271 cw(c17.865,18.991) 17.145,18.991 cw(c17.865,18.991) 17.865,19.711 cw(c17.865,18.991) 18.585,18.991 cw(c17.865,18.991)
  pour cut-out: 52.038,79.072 cw(c52.038,87.072) 44.038,87.072 cw(c52.038,87.072) 52.038,95.072 cw(c52.038,87.072) 60.038,87.072 cw(c52.038,87.072)
  pour cut-out: 15.119,157.57 cw(c15.119,158.29) 14.399,158.29 cw(c15.119,158.29) 15.119,159.01 cw(c15.119,158.29) 15.839,158.29 cw(c15.119,158.29)
  pour cut-out: 12.923,157.302 cw(c12.923,158.022) 12.203,158.022 cw(c12.923,158.022) 12.923,158.742 cw(c12.923,158.022) 13.643,158.022 cw(c12.923,158.022)
  pour cut-out: 11.02,156.256 cw(c11.02,156.976) 10.3,156.976 cw(c11.02,156.976) 11.02,157.696 cw(c11.02,156.976) 11.74,156.976 cw(c11.02,156.976)
  pour cut-out: 5.627,164.03 cw(c5.627,164.75) 4.907,164.75 cw(c5.627,164.75) 5.627,165.47 cw(c5.627,164.75) 6.347,164.75 cw(c5.627,164.75)
  pour cut-out: 5.768,153.639 cw(c5.768,154.359) 5.048,154.359 cw(c5.768,154.359) 5.768,155.079 cw(c5.768,154.359) 6.488,154.359 cw(c5.768,154.359)
  pour cut-out: 6.589,152.318 cw(c6.589,153.038) 5.869,153.038 cw(c6.589,153.038) 6.589,153.758 cw(c6.589,153.038) 7.309,153.038 cw(c6.589,153.038)
  pour cut-out: 6.589,150.718 cw(c6.589,151.438) 5.869,151.438 cw(c6.589,151.438) 6.589,152.158 cw(c6.589,151.438) 7.309,151.438 cw(c6.589,151.438)
  pour cut-out: 6.31,149.551 cw(c6.31,150.271) 5.59,150.271 cw(c6.31,150.271) 6.31,150.991 cw(c6.31,150.271) 7.03,150.271 cw(c6.31,150.271)
  pour cut-out: 6.25,24.875 cw(c6.25,25.595) 5.53,25.595 cw(c6.25,25.595) 6.25,26.315 cw(c6.25,25.595) 6.97,25.595 cw(c6.25,25.595)
  pour cut-out: 37.639,114.437 38.775,114.437 41,112.212 41,111.936 37.672,111.936 37.639,111.969
  pour cut-out: 23.491,8.148 22.8,8.169 22.43,8.453 22.43,14.592 22.622,14.784 23.607,14.784 23.851,14.54 23.851,8.428
  pour cut-out: 63,130.25 63,126.056 63.785,125.271 64.5,125.271 64.5,130.25
  pour cut-out: 62.986,111.714 62.986,115.908 63.772,116.693 64.486,116.693 64.486,111.713
  pour cut-out: 63.251,157.122 64.592,157.122 64.753,156.961 64.753,154.419 64.501,154.167 63.275,154.167 63.04,154.401 63.04,156.911
  pour cut-out: 22.994,147.936 22.75,148.437 22.75,152.749 22.943,152.942 23.927,152.942 24.172,152.697 24.172,148.437 23.927,147.936
  pour cut-out: 10.564,154.799 11.055,155.291 20.429,155.291 20.914,154.805 20.914,153.478 20.404,152.967 11.056,152.967 10.564,153.46
  pour cut-out: 10.559,164.447 11.021,164.91 20.843,164.91 21.243,164.509 21.243,158.706 20.857,158.319 10.903,158.319 10.559,158.663
  pour cut-out: 63.101,87.166 64.442,87.166 64.604,87.005 64.604,84.463 64.351,84.211 63.125,84.211 62.89,84.446 62.89,86.956
  pour cut-out: 24.692,161.794 24.989,162.09 27.324,162.09 27.42,161.994 27.42,160.456 27.043,160.078 24.977,160.078 24.692,160.363
  pour cut-out: 63.251,19.14 64.592,19.14 64.753,18.979 64.753,16.437 64.501,16.185 63.275,16.185 63.04,16.419 63.04,18.929
  pour cut-out: 10.372,27.538 10.834,28 20.656,28 21.057,27.599 21.057,21.796 20.67,21.409 10.716,21.409 10.372,21.754
  pour cut-out: 28.699,22.801 28.699,24.834 25.5,24.834 24.979,24.313 24.979,23.27 25.447,22.801
  text ".Layer_Name" at 15.194,-21.806 h1.52
Layer 4:
  rectangle net B+_2: 5.479,29.204 21.945,31.729
  rectangle net Pri-Mid1_2: 35.515,3.537 37.264,7.513
  rectangle net Pri-Mid1_2: 27.053,3.657 28.725,7.513
  rectangle net Pri-SW_2: 11.654,21.986 20.482,27.321
  pour cut-out: 6.31,149.551 cw(c6.31,150.271) 5.59,150.271 cw(c6.31,150.271) 6.31,150.991 cw(c6.31,150.271) 7.03,150.271 cw(c6.31,150.271)
  pour cut-out: 6.589,150.718 cw(c6.589,151.438) 5.869,151.438 cw(c6.589,151.438) 6.589,152.158 cw(c6.589,151.438) 7.309,151.438 cw(c6.589,151.438)
  pour cut-out: 6.589,152.318 cw(c6.589,153.038) 5.869,153.038 cw(c6.589,153.038) 6.589,153.758 cw(c6.589,153.038) 7.309,153.038 cw(c6.589,153.038)
  pour cut-out: 5.768,153.639 cw(c5.768,154.359) 5.048,154.359 cw(c5.768,154.359) 5.768,155.079 cw(c5.768,154.359) 6.488,154.359 cw(c5.768,154.359)
  pour cut-out: 5.627,164.03 cw(c5.627,164.75) 4.907,164.75 cw(c5.627,164.75) 5.627,165.47 cw(c5.627,164.75) 6.347,164.75 cw(c5.627,164.75)
  pour cut-out: 11.02,156.256 cw(c11.02,156.976) 10.3,156.976 cw(c11.02,156.976) 11.02,157.696 cw(c11.02,156.976) 11.74,156.976 cw(c11.02,156.976)
  pour cut-out: 12.923,157.302 cw(c12.923,158.022) 12.203,158.022 cw(c12.923,158.022) 12.923,158.742 cw(c12.923,158.022) 13.643,158.022 cw(c12.923,158.022)
  pour cut-out: 15.119,157.57 cw(c15.119,158.29) 14.399,158.29 cw(c15.119,158.29) 15.119,159.01 cw(c15.119,158.29) 15.839,158.29 cw(c15.119,158.29)
  pour cut-out: 52.038,79.072 cw(c52.038,87.072) 44.038,87.072 cw(c52.038,87.072) 52.038,95.072 cw(c52.038,87.072) 60.038,87.072 cw(c52.038,87.072)
  pour cut-out: 6.25,24.875 cw(c6.25,25.595) 5.53,25.595 cw(c6.25,25.595) 6.25,26.315 cw(c6.25,25.595) 6.97,25.595 cw(c6.25,25.595)
  pour cut-out: 37.639,114.437 38.775,114.437 41,112.212 41,111.936 37.672,111.936 37.639,111.969
  pour cut-out: 10.559,164.447 11.021,164.91 20.843,164.91 21.243,164.509 21.243,158.706 20.857,158.319 10.903,158.319 10.559,158.663
  pour cut-out: 10.564,154.799 11.055,155.291 20.429,155.291 20.914,154.805 20.914,153.478 20.404,152.967 11.056,152.967 10.564,153.46
  pour cut-out: 22.994,147.936 22.75,148.437 22.75,152.749 22.943,152.942 23.927,152.942 24.172,152.697 24.172,148.437 23.927,147.936
  pour cut-out: 63,130.25 63,126.056 63.785,125.271 64.5,125.271 64.5,130.25
  pour cut-out: 62.986,111.714 62.986,115.908 63.772,116.693 64.486,116.693 64.486,111.713
  pour cut-out: 36.508,51.807 36.508,53.148 36.757,53.397 38.88,53.397 39.275,53.002 39.275,51.904 38.898,51.526 36.789,51.526
  pour cut-out: 24.534,161.537 25.088,162.09 26.904,162.09 27.42,161.574 27.42,160.456 27.043,160.078 24.977,160.078 24.534,160.521
  pour cut-out: 32.274,22.438 52.276,19.373 52.276,18.693 32.139,21.889
  pour cut-out: 63.251,19.14 64.592,19.14 64.753,18.979 64.753,16.437 64.501,16.185 63.275,16.185 63.04,16.419 63.04,18.929
  text ".Layer_Name" at 15.405,-21.806 h1.52
Layer 5:
  rectangle net B+_2: 5.479,29.71 21.197,31.729
  rectangle net Pri-SW_2: 21.821,29.443 24.74,34.307
  rectangle net Pri-Mid1_2: 35.515,3.537 37.264,7.513
  pour cut-out: 15.119,157.57 cw(c15.119,158.29) 14.399,158.29 cw(c15.119,158.29) 15.119,159.01 cw(c15.119,158.29) 15.839,158.29 cw(c15.119,158.29)
  pour cut-out: 12.923,157.302 cw(c12.923,158.022) 12.203,158.022 cw(c12.923,158.022) 12.923,158.742 cw(c12.923,158.022) 13.643,158.022 cw(c12.923,158.022)
  pour cut-out: 11.02,156.256 cw(c11.02,156.976) 10.3,156.976 cw(c11.02,156.976) 11.02,157.696 cw(c11.02,156.976) 11.74,156.976 cw(c11.02,156.976)
  pour cut-out: 5.627,164.03 cw(c5.627,164.75) 4.907,164.75 cw(c5.627,164.75) 5.627,165.47 cw(c5.627,164.75) 6.347,164.75 cw(c5.627,164.75)
  pour cut-out: 5.768,153.639 cw(c5.768,154.359) 5.048,154.359 cw(c5.768,154.359) 5.768,155.079 cw(c5.768,154.359) 6.488,154.359 cw(c5.768,154.359)
  pour cut-out: 6.589,152.318 cw(c6.589,153.038) 5.869,153.038 cw(c6.589,153.038) 6.589,153.758 cw(c6.589,153.038) 7.309,153.038 cw(c6.589,153.038)
  pour cut-out: 6.589,150.718 cw(c6.589,151.438) 5.869,151.438 cw(c6.589,151.438) 6.589,152.158 cw(c6.589,151.438) 7.309,151.438 cw(c6.589,151.438)
  pour cut-out: 6.31,149.551 cw(c6.31,150.271) 5.59,150.271 cw(c6.31,150.271) 6.31,150.991 cw(c6.31,150.271) 7.03,150.271 cw(c6.31,150.271)
  pour cut-out: 52.038,79.072 cw(c52.038,87.072) 44.038,87.072 cw(c52.038,87.072) 52.038,95.072 cw(c52.038,87.072) 60.038,87.072 cw(c52.038,87.072)
  pour cut-out: 6.25,24.875 cw(c6.25,25.595) 5.53,25.595 cw(c6.25,25.595) 6.25,26.315 cw(c6.25,25.595) 6.97,25.595 cw(c6.25,25.595)
  pour cut-out: 41.094,115.914 42.614,115.914 43.122,115.406 43.122,113.701 42.645,113.223 41.094,113.223
  pour cut-out: 10.564,154.799 11.055,155.291 20.429,155.291 20.914,154.805 20.914,153.478 20.404,152.967 11.056,152.967 10.564,153.46
  pour cut-out: 22.994,147.936 22.75,148.437 22.75,152.749 22.943,152.942 23.927,152.942 24.172,152.697 24.172,148.437 23.927,147.936
  pour cut-out: 63,130.25 63,126.056 63.785,125.271 64.5,125.271 64.5,130.25
  pour cut-out: 62.986,111.714 62.986,115.908 63.772,116.693 64.486,116.693 64.486,111.713
  pour cut-out: 10.559,164.447 11.021,164.91 20.843,164.91 21.243,164.509 21.243,158.706 20.857,158.319 10.903,158.319 10.559,158.663
  pour cut-out: 24.945,160.25 26.83,160.25 27.338,159.742 27.338,158.037 26.86,157.56 24.954,157.56 24.495,158.019 24.495,159.799
  pour cut-out: 63.251,19.14 64.592,19.14 64.753,18.979 64.753,16.437 64.501,16.185 63.275,16.185 63.04,16.419 63.04,18.929
  pour cut-out: 32.274,22.438 52.276,19.373 52.276,18.693 32.139,21.889
  text ".Layer_Name" at 15.418,-21.806 h1.52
